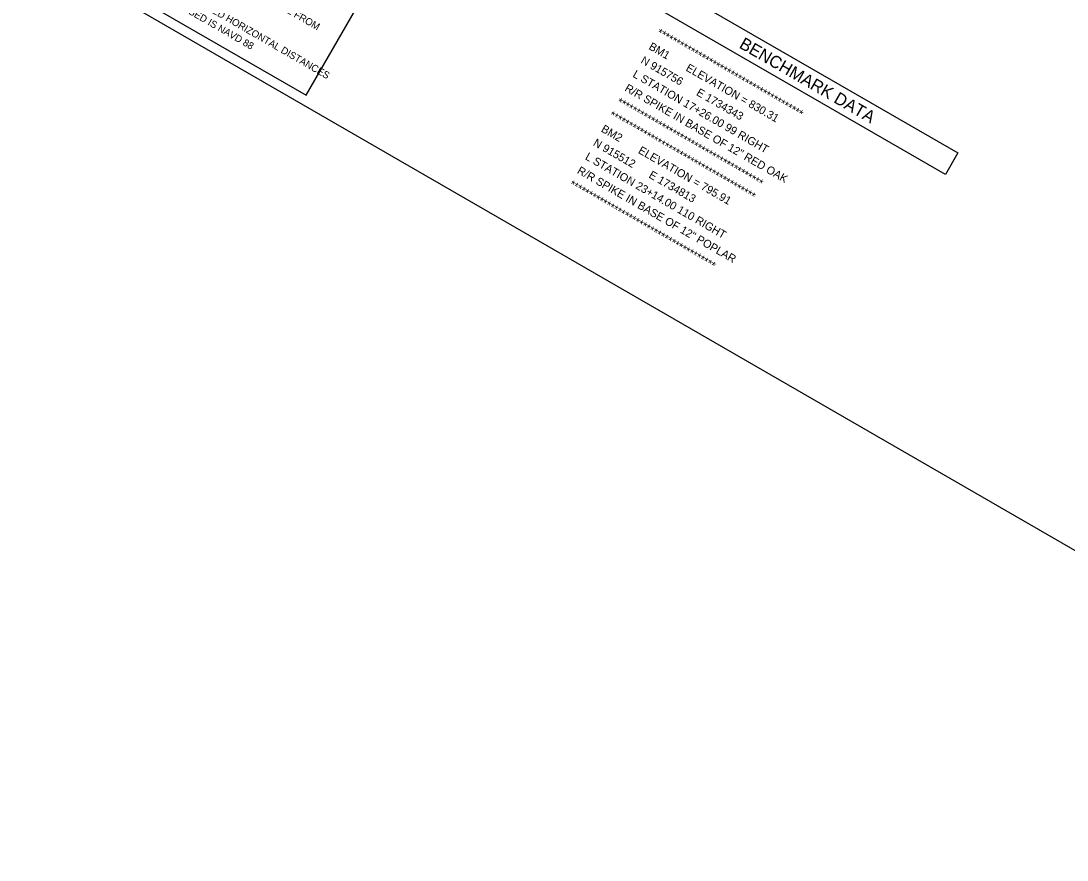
# Model space of a CAD drawing. Extents: x 1729269 to 1736953, y 913137 to 919486.
# Drawn here: x 1729870 to 1733139, y 913137 to 915759 of the extents above; entities that cross this region are included whole.
import ezdxf

# ---------------------------------------------------------------- set-up
doc = ezdxf.new("R2010")
doc.units = 0
for name, color, linetype in [('CTL Sheet Border CELL', 7, 'Continuous'), ('CTL Sheet Datum Description CELL', 7, 'Continuous'), ('CTL Sheet Text', 7, 'Continuous')]:
    doc.layers.add(name, color=color, linetype=linetype)

msp = doc.modelspace()

# ---------------------------------------------------------------- linework, layer by layer
at = {"layer": 'CTL Sheet Border CELL'}
for points in [[(1736848.9, 916616.2), (1731878.6, 919485.8), (1729869.9, 916006.6), (1734840.2, 913137)], [(1731909.6, 915858.7), (1732797.3, 915346.2), (1732758.4, 915278.9), (1731870.8, 915791.3)]]:
    msp.add_lwpolyline(points, close=True, dxfattribs=at)
at = {"layer": 'CTL Sheet Datum Description CELL'}
msp.add_lwpolyline([(1729908.8, 916018.4), (1730761, 915526.4), (1731099, 916111.9), (1730246.8, 916603.9)], close=True, dxfattribs=at)

# ---------------------------------------------------------------- texts
for s, p in [('LOCALIZED HORIZONTAL GROUND DISTANCE FROM', (1730140.8, 916107)), ('ALL LINEAR DIMENSIONS ARE LOCALIZED HORIZONTAL DISTANCES', (1729976, 916067.2)), ('VERTICAL DATUM USED IS NAVD 88', (1730142.2, 915926.2))]:
    msp.add_text(s, height=22.14, rotation=330, dxfattribs=at).set_placement(p)
at = {"layer": 'CTL Sheet Text'}
for s, height, p in [('****************************************', 25, (1731854.4, 915715)), ('BENCHMARK DATA', 38.26, (1732111.4, 915676.3)), ('BM1       ELEVATION = 830.31', 25, (1731829.4, 915671.7)), ('N 915756      E 1734343', 25, (1731804.4, 915628.4)), ('L STATION 17+26.00 99 RIGHT', 25, (1731779.4, 915585.1)), ('R/R SPIKE IN BASE OF 12" RED OAK', 25, (1731754.4, 915541.8)), ('****************************************', 25, (1731729.4, 915498.5)), ('****************************************', 25, (1731705.7, 915457.4)), ('BM2       ELEVATION = 795.91', 25, (1731680.7, 915414.1)), ('N 915512      E 1734813', 25, (1731655.7, 915370.8)), ('L STATION 23+14.00 110 RIGHT', 25, (1731630.7, 915327.5)), ('R/R SPIKE IN BASE OF 12" POPLAR', 25, (1731605.7, 915284.2)), ('****************************************', 25, (1731580.7, 915240.9))]:
    msp.add_text(s, height=height, rotation=330, dxfattribs=at).set_placement(p)

doc.saveas('drawing.dxf')
